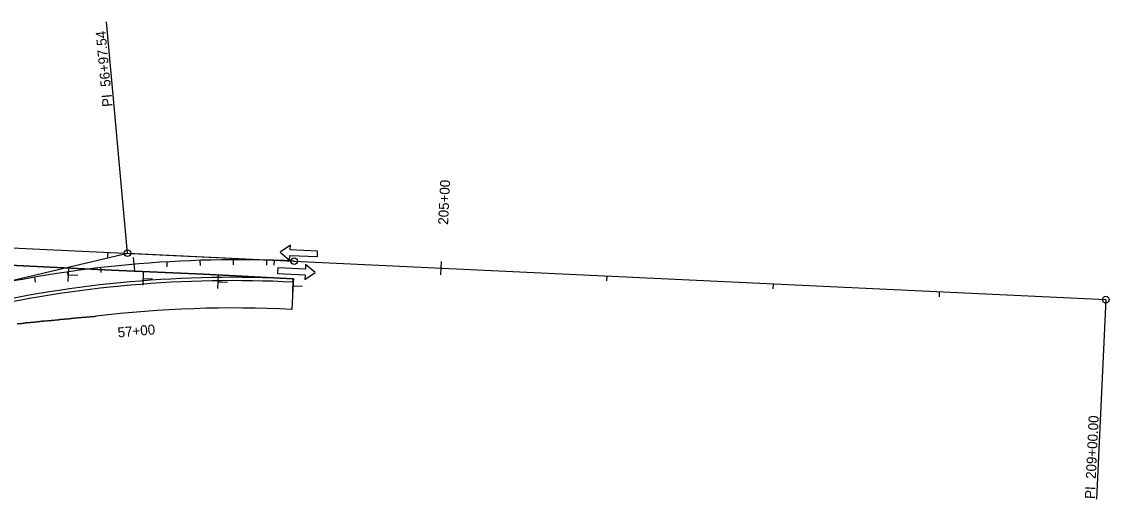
# Model space of a CAD drawing. Extents: x 1140339 to 1165793, y 1646213 to 1669071.
# Drawn here: x 1149481 to 1150134, y 1657315 to 1657601 of the extents above; entities that cross this region are included whole.
import ezdxf

# ---------------------------------------------------------------- set-up
doc = ezdxf.new("R2010")
doc.units = 0
for name, color, linetype in [('R_Horz Alg', 7, 'Continuous'), ('R_Horz Alg Annot', 7, 'Continuous'), ('R_MOT', 7, 'Continuous'), ('R_No Plot', 7, 'Continuous'), ('R_Proposed Const Limits_Fill', 7, 'Continuous'), ('R_Proposed Road_Lane', 7, 'Continuous'), ('R_Proposed Road_Shoulder', 7, 'Continuous')]:
    doc.layers.add(name, color=color, linetype=linetype)

msp = doc.modelspace()

# ---------------------------------------------------------------- linework, layer by layer
at = {"layer": 'R_Horz Alg'}
msp.add_line((1148434, 1657515.04), (1150132.09, 1657434.46), dxfattribs=at)
msp.add_arc((1149610.54, 1656742.21), 716.2, 87.28333, 103.21228, dxfattribs=at)
at = {"layer": 'R_Horz Alg Annot'}
for p, q in [((1149446.85, 1657439.45), (1149544.4, 1657462.35)), ((1149544.4, 1657462.35), (1149644.49, 1657457.6))]:
    msp.add_line(p, q, dxfattribs=at)
for points in [[(1149544.4, 1657462.35), (1149531.64, 1657601.32)], [(1149532.62, 1657459.91), (1149532.76, 1657462.9)], [(1149547.79, 1657459.67), (1149548.48, 1657451.7)], [(1149568.26, 1657454.15), (1149568.08, 1657457.15)], [(1149588.15, 1657455.05), (1149588.06, 1657458.05)], [(1149608.07, 1657455.4), (1149608.05, 1657458.4)], [(1149627.98, 1657455.19), (1149628.05, 1657458.19)], [(1149632.51, 1657455.17), (1149632.65, 1657458.16)], [(1149732.72, 1657457.42), (1149732.35, 1657449.43)], [(1149508.83, 1657448.12), (1149508.4, 1657451.09)], [(1149528.58, 1657450.68), (1149528.24, 1657453.66)], [(1149489.16, 1657445), (1149488.65, 1657447.96)], [(1149832.28, 1657445.69), (1149832.42, 1657448.68)], [(1149932.17, 1657440.95), (1149932.31, 1657443.94)], [(1150032.06, 1657436.21), (1150032.2, 1657439.2)], [(1150132.09, 1657434.46), (1150126.4, 1657314.6)]]:
    msp.add_lwpolyline(points, dxfattribs=at)
for centre in [(1149544.4, 1657462.35), (1149644.49, 1657457.6), (1150132.09, 1657434.46)]:
    msp.add_circle(centre, 2, dxfattribs=at)
at = {"layer": 'R_MOT'}
for p, q in [((1149508.76, 1657445.33), (1149509.09, 1657453.32)), ((1149553.73, 1657443.19), (1149554.06, 1657451.18)), ((1149509.04, 1657449.3), (1149514.5, 1657449.07)), ((1149554.01, 1657447.16), (1149559.46, 1657446.94)), ((1149598.66, 1657441.11), (1149598.99, 1657449.11)), ((1149598.94, 1657445.09), (1149604.39, 1657444.86)), ((1149643.6, 1657438.84), (1149643.93, 1657446.84)), ((1149643.88, 1657442.82), (1149649.34, 1657442.59))]:
    msp.add_line(p, q, dxfattribs=at)
for points in [[(1149642.18, 1657467.22), (1149636.13, 1657463), (1149641.75, 1657458.23), (1149641.88, 1657461.04), (1149658.42, 1657460.26), (1149658.58, 1657463.63), (1149642.04, 1657464.41)], [(1149650.94, 1657446.53), (1149656.99, 1657450.74), (1149651.37, 1657455.52), (1149651.24, 1657452.71), (1149634.7, 1657453.49), (1149634.54, 1657450.12), (1149651.08, 1657449.34)]]:
    msp.add_lwpolyline(points, close=True, dxfattribs=at)
at = {"layer": 'R_No Plot'}
for p, q in [((1149643.88, 1657444.96), (1149643.05, 1657428.56)), ((1149643.98, 1657446.96), (1149643.88, 1657444.96))]:
    msp.add_line(p, q, dxfattribs=at)
for points in [[(1149456.99, 1657456.08), (1149461.68, 1657455.84), (1149477.76, 1657455.02), (1149493.85, 1657454.2), (1149514.25, 1657453.18), (1149534.65, 1657452.17), (1149548.5, 1657451.54), (1149562.35, 1657450.92), (1149576.21, 1657450.3), (1149590.06, 1657449.68), (1149605.38, 1657448.9), (1149620.71, 1657448.13), (1149636.03, 1657447.36), (1149643.98, 1657446.96)], [(1149525.47, 1657424.45), (1149524.55, 1657424.37), (1149521.99, 1657424.15), (1149519.39, 1657423.93), (1149514.24, 1657423.47), (1149512.41, 1657423.3), (1149509.08, 1657422.99), (1149503.93, 1657422.49), (1149502.83, 1657422.38), (1149498.77, 1657422), (1149493.6, 1657421.51), (1149493.22, 1657421.48), (1149488.43, 1657420.98), (1149483.62, 1657420.47), (1149483.26, 1657420.43), (1149480.94, 1657420.17), (1149478.09, 1657419.83)]]:
    msp.add_lwpolyline(points, dxfattribs=at)
msp.add_arc((1149608.18, 1656741.99), 687.45, 87.09231, 96.90964, dxfattribs=at)
at = {"layer": 'R_Proposed Const Limits_Fill'}
msp.add_line((1149643.88, 1657444.96), (1149643.05, 1657428.56), dxfattribs=at)
msp.add_lwpolyline([(1149478.09, 1657419.83), (1149480.94, 1657420.17), (1149483.26, 1657420.43), (1149483.62, 1657420.47), (1149488.43, 1657420.98), (1149493.22, 1657421.48), (1149493.6, 1657421.51), (1149498.77, 1657422), (1149502.83, 1657422.38), (1149503.93, 1657422.49), (1149509.08, 1657422.99), (1149512.41, 1657423.3), (1149514.24, 1657423.47), (1149519.39, 1657423.93), (1149521.99, 1657424.15), (1149524.55, 1657424.37), (1149525.47, 1657424.45)], dxfattribs=at)
msp.add_arc((1149608.18, 1656741.99), 687.45, 87.09231, 96.90964, dxfattribs=at)
at = {"layer": 'R_Proposed Road_Lane'}
msp.add_line((1149643.98, 1657446.96), (1149643.88, 1657444.96), dxfattribs=at)
msp.add_lwpolyline([(1149643.98, 1657446.96), (1149636.03, 1657447.36), (1149620.71, 1657448.13), (1149605.38, 1657448.9), (1149590.06, 1657449.68), (1149576.21, 1657450.3), (1149562.35, 1657450.92), (1149548.5, 1657451.54), (1149534.65, 1657452.17), (1149514.25, 1657453.18), (1149493.85, 1657454.2), (1149477.76, 1657455.02), (1149461.68, 1657455.84), (1149456.99, 1657456.08)], dxfattribs=at)
msp.add_arc((1149608.18, 1656741.99), 705.87, 87.09231, 103.02126, dxfattribs=at)
at = {"layer": 'R_Proposed Road_Shoulder'}
msp.add_arc((1149608.18, 1656741.99), 703.87, 87.09231, 103.02126, dxfattribs=at)

# ---------------------------------------------------------------- texts
at = {"layer": 'R_Horz Alg Annot'}
for s, rotation, p in [('PI  56+97.54', 95.24781, (1149535.37, 1657550.52)), ('205+00', 87.28333, (1149736.91, 1657479.31)), ('57+00', 4.99914, (1149538.73, 1657411.7)), ('PI  209+00.00', 87.28333, (1150125.4, 1657314.65))]:
    msp.add_text(s, height=6, rotation=rotation, dxfattribs=at).set_placement(p)

doc.saveas('drawing.dxf')
